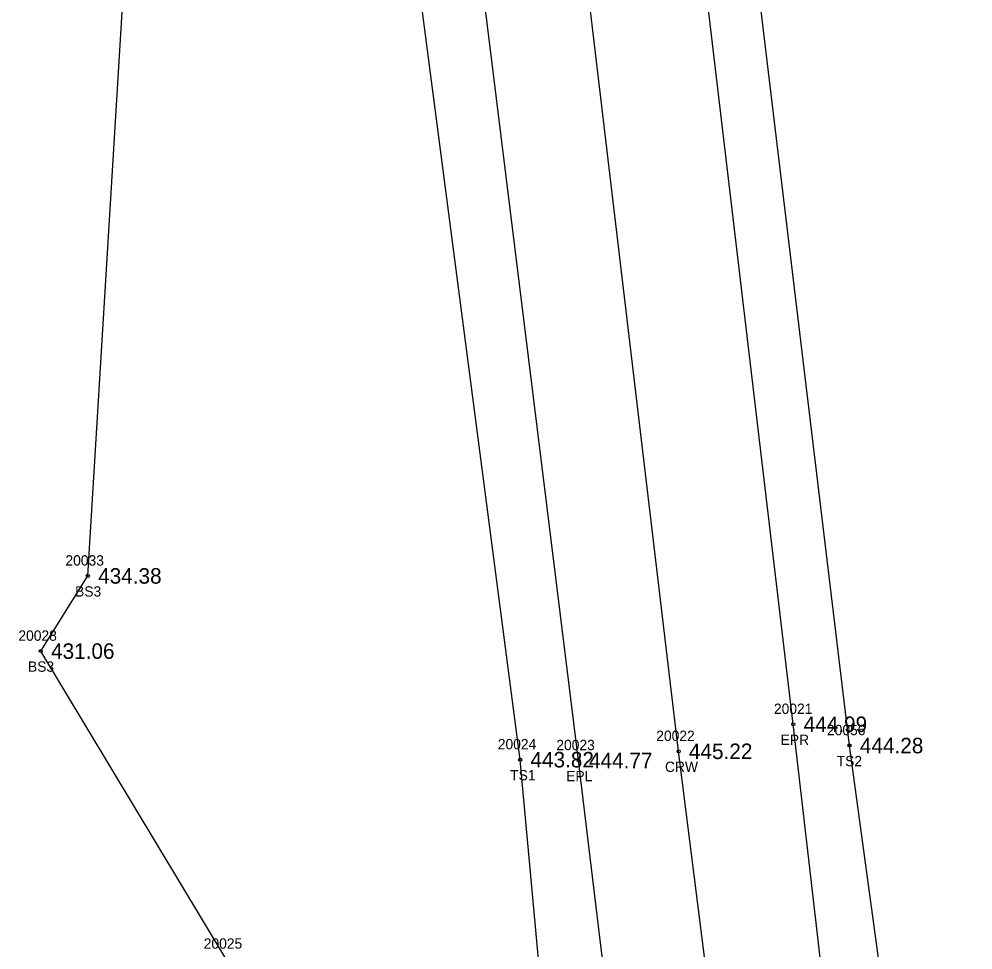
# Model space of a CAD drawing. Extents: x 1858461 to 1858936, y 1147060 to 1148183.
# Drawn here: x 1858649.7 to 1858741.9, y 1147350.4 to 1147440.4 of the extents above; entities that cross this region are included whole.
import ezdxf

# ---------------------------------------------------------------- set-up
doc = ezdxf.new("R2010")
doc.units = 0
for name, color, linetype in [('RD_DTM_BkLn1', 7, 'Continuous'), ('RD_DTM_BkLn2', 7, 'Continuous'), ('RD_DTM_BkLn_txCode', 7, 'Continuous'), ('RD_EX_Road', 7, 'Continuous'), ('RD_EX_Road_txCode', 7, 'Continuous'), ('RD_EX_TX_Misc_ELEV', 7, 'Continuous'), ('RD_EX_TX_Road_ELEV', 7, 'Continuous'), ('RD_HC_Survey_ELEV', 7, 'Continuous'), ('RD_HC_Survey_txCode', 7, 'Continuous'), ('RD_SMD_Locator', 7, 'Continuous')]:
    doc.layers.add(name, color=color, linetype=linetype)

msp = doc.modelspace()

# ---------------------------------------------------------------- linework, layer by layer
at = {"layer": 'RD_DTM_BkLn1'}
msp.add_lwpolyline([(1858749.221, 1147073.218), (1858736.714, 1147171.733), (1858725.838, 1147271.146), (1858713.418, 1147369.587), (1858701.549, 1147469.388), (1858689.318, 1147570.787)], dxfattribs=at)
at = {"layer": 'RD_DTM_BkLn2'}
for points in [[(1858714.737, 1147067.605), (1858710.559, 1147167.021), (1858688.241, 1147264.231), (1858669.682, 1147349.506), (1858651.767, 1147379.273), (1858656.318, 1147386.543), (1858661.336, 1147469.114), (1858657.398, 1147555.084), (1858671.869, 1147580.016)], [(1858771.939, 1147076.946), (1858754.289, 1147172.99), (1858743.317, 1147272.091), (1858729.943, 1147370.143), (1858717.876, 1147470.383), (1858711.02, 1147558.858), (1858710.287, 1147569.233), (1858703.018, 1147572.691)], [(1858727.7, 1147071.224), (1858717.511, 1147168.604), (1858707.401, 1147267.827), (1858698.103, 1147368.777), (1858685.199, 1147467.746), (1858675.58, 1147560.053), (1858676.786, 1147568.869)]]:
    msp.add_lwpolyline(points, dxfattribs=at)
at = {"layer": 'RD_EX_Road'}
for points in [[(1858760.329, 1147074.172), (1858747.614, 1147172.63), (1858736.076, 1147271.966), (1858724.509, 1147372.199), (1858712.855, 1147470.384), (1858700.055, 1147571.957), (1858689.318, 1147570.787)], [(1858739.577, 1147072.318), (1858726.74, 1147170.579), (1858715.698, 1147269.682), (1858703.759, 1147368.695), (1858691.45, 1147468.107), (1858680.497, 1147569.647), (1858689.318, 1147570.787)]]:
    msp.add_lwpolyline(points, dxfattribs=at)
at = {"layer": 'RD_SMD_Locator'}
for centre in [(1858656.318, 1147386.543), (1858651.767, 1147379.273), (1858724.509, 1147372.199), (1858729.943, 1147370.143), (1858698.103, 1147368.777), (1858713.418, 1147369.587), (1858703.759, 1147368.695)]:
    msp.add_circle(centre, 0.15, dxfattribs=at)

# ---------------------------------------------------------------- texts
at = {"layer": 'RD_DTM_BkLn_txCode'}
for s, p in [('20033', (1858654.16, 1147387.543)), ('BS3', (1858655.089, 1147384.543)), ('20028', (1858649.61, 1147380.273)), ('BS3', (1858650.539, 1147377.273)), ('20056', (1858727.762, 1147371.143)), ('20024', (1858695.945, 1147369.777)), ('TS2', (1858728.699, 1147368.143)), ('TS1', (1858697.142, 1147366.777)), ('20025', (1858667.525, 1147350.506))]:
    msp.add_text(s, height=1, dxfattribs=at).set_placement(p)
at = {"layer": 'RD_EX_Road_txCode'}
for s, p in [('20021', (1858722.635, 1147373.199)), ('20023', (1858701.602, 1147369.695)), ('EPR', (1858723.281, 1147370.199)), ('EPL', (1858702.554, 1147366.695))]:
    msp.add_text(s, height=1, dxfattribs=at).set_placement(p)
at = {"layer": 'RD_EX_TX_Misc_ELEV'}
for s, p in [('434.38', (1858657.318, 1147385.793)), ('431.06', (1858652.767, 1147378.523)), ('444.28', (1858730.943, 1147369.393)), ('443.82', (1858699.103, 1147368.027))]:
    msp.add_text(s, height=1.5, dxfattribs=at).set_placement(p)
at = {"layer": 'RD_EX_TX_Road_ELEV'}
for s, p in [('444.99', (1858725.509, 1147371.449)), ('444.77', (1858704.759, 1147367.945))]:
    msp.add_text(s, height=1.5, dxfattribs=at).set_placement(p)
at = {"layer": 'RD_HC_Survey_ELEV'}
msp.add_text('445.22', height=1.5, dxfattribs=at).set_placement((1858714.418, 1147368.837))
at = {"layer": 'RD_HC_Survey_txCode'}
for s, p in [('20022', (1858711.261, 1147370.587)), ('CRW', (1858712.103, 1147367.587))]:
    msp.add_text(s, height=1, dxfattribs=at).set_placement(p)

doc.saveas('drawing.dxf')
